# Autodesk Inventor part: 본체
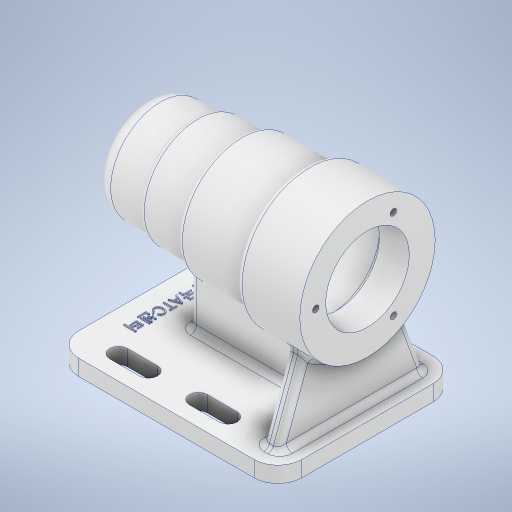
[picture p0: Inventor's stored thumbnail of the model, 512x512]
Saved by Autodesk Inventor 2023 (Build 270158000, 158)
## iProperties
Created: 2022-07
Part Number: 본체
Material: 알루미늄 6061
Document SubType Name: Modeling
Designer: owner
Density: 2.7 g/cm^3
Appearance: 알루미늄 - 평지
Mass: 695.707 g
Surface Area: 710.79 cm^2
Volume: 257.669 cm^3
Author: owner
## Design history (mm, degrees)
sketch "스케치1"
  geometry: L1 (0, 0)-(0, 34); L2 (0, 34)-(-32, 34); L3 (-32, 34)-(-32, 30); L4 (-32, 30)-(-66, 30); L5 (-66, 30)-(-66, 27); L6 (-66, 27)-(-88, 27); L7 (-88, 27)-(-88, 25); L8 (-88, 25)-(-104, 25); L9 (-112, 17)-(-112, 0); L10 (-112, 0)-(0, 0); L11 (0, 21)-(-15, 21); L12 (-15, 21)-(-15, 21); L13 (-18, 24)-(-66, 24); L14 (-69, 21)-(-69, 21); L15 (-69, 21)-(-80.7, 21); L16 (-81, 20.7)-(-81, 17.5); L17 (-81, 17.5)-(-98.7, 17.5); L18 (-99, 17.2)-(-99, 16); L19 (-99, 16)-(-102.7, 16); L20 (-103, 15.7)-(-103, 10.5); L21 (-103, 10.5)-(-103, 10.5); L22 (-106, 7.5)-(-106, 0); A1 r 8 centre (-104, 17) between (-104, 25) and (-112, 17); A2 r 0.3 centre (-102.7, 15.7) between (-102.7, 16) and (-103, 15.7); A3 r 0.3 centre (-98.7, 17.2) between (-98.7, 17.5) and (-99, 17.2); A4 r 0.3 centre (-80.7, 20.7) between (-80.7, 21) and (-81, 20.7); A5 r 3 centre (-66, 21) between (-66, 24) and (-69, 21); A6 r 3 centre (-18, 21) between (-15, 21) and (-18, 24); A7 r 3 centre (-103, 7.5) between (-103, 10.5) and (-106, 7.5); 4 further points
  constraints: 44 end point, 19 perpendicular, 14 point on circle, 14 tangent, 7 centre point, 4 equal radius, 4 point on line, 2 vertical, 1 horizontal
  dimensions: "d0" = 34 distance of L1.start L1.end; "d1" = 25 distance between parallel lines of L10 L8; "d2" = 112 distance between parallel lines of L1 L9; "d3" = 24 distance between parallel lines of L7 L9; "d4" = 22 distance between parallel lines of L5 L7; "d5" = 34 distance between parallel lines of L3 L5; "d6" = 27 distance between parallel lines of L10 L6; "d7" = 30 distance between parallel lines of L10 L4; "d8" = 21 distance between parallel lines of L10 L11; "d9" = 15 distance between parallel lines of L1 L12; "d10" = 54 distance between parallel lines of L14 L12; "d11" = 24 distance between parallel lines of L10 L13; "d12" = 12 distance between parallel lines of L16 L14; "d13" = 21 distance between parallel lines of L10 L15; "d14" = 18 distance between parallel lines of L18 L16; "d15" = 17.5 distance between parallel lines of L10 L17; "d16" = 10.5 distance between parallel lines of L10 L21; "d17" = 4 distance of L18.end point (-103, 16); "d18" = 16 distance between parallel lines of L10 L19; "d19" = 3 distance between parallel lines of L22 L20; "d20" = 8 radius of A1; "d21" = 0.3 radius of A2; "d22" = 3 radius of A5
revolve "회전1" sketch "스케치1" stored, may be unused: angle "d23" = 90 deg
node "작업 평면1"
sketch "스케치2"
  geometry: L1 (0, 0)-(0, -45); L2 (0, -45)-(112, -45); L3 (112, -45)-(112, 0); L4 (112, 0)-(0, 0); L5 (0, 45)-(112, 45); L6 (112, 45)-(112, 0); L7 (0, 0)-(0, 45)
  constraints: 14 end point, 2 perpendicular, 2 symmetric about line, 2 vertical
  dimensions: "d27" = 45 distance between parallel lines of L4 L2; "d28" = 112 distance between parallel lines of L1 L3
extrude "돌출1" join sketch "스케치2" distance "d29" = 8; taper "d30" = 0 deg
fillet "모깎기1" dims "d31" = 12
sketch "스케치4"
  geometry: 1 further point
sketch "스케치5"
  geometry: L1 (-92, -33)-(-77, -33); L2 (-92, -37.5)-(-77, -37.5); L3 (-77, -28.5)-(-92, -28.5); L4 (-112, 33)-(-112, -33) reference; L5 (-100, -45)-(-12, -45) reference; L6 (-52, -33)-(-37, -33); L7 (-52, -37.5)-(-37, -37.5); L8 (-37, -28.5)-(-52, -28.5); L9 (-92, 33)-(-77, 33); L10 (-92, 28.5)-(-77, 28.5); L11 (-77, 37.5)-(-92, 37.5); L12 (-12, 45)-(-100, 45) reference; L13 (-52, 33)-(-37, 33); L14 (-52, 28.5)-(-37, 28.5); L15 (-37, 37.5)-(-52, 37.5); A1 r 4.5 centre (-92, -33) between (-92, -28.5) and (-92, -37.5); A2 r 4.5 centre (-77, -33) between (-77, -37.5) and (-77, -28.5); A3 r 4.5 centre (-52, -33) between (-52, -28.5) and (-52, -37.5); A4 r 4.5 centre (-37, -33) between (-37, -37.5) and (-37, -28.5); A5 r 4.5 centre (-92, 33) between (-92, 37.5) and (-92, 28.5); A6 r 4.5 centre (-77, 33) between (-77, 28.5) and (-77, 37.5); A7 r 4.5 centre (-52, 33) between (-52, 37.5) and (-52, 28.5); A8 r 4.5 centre (-37, 33) between (-37, 28.5) and (-37, 37.5); 5 further points
  constraints: 32 end point, 16 point on circle, 16 tangent, 8 centre point, 4 horizontal, 4 midpoint, 4 parallel
  dimensions: "d38" = 9 diameter of A2; "d39" = 20 distance from line of L1.start L4; "d40" = 12 distance from line of L5 point (-84.5, -33); "d41" = 15 distance of L1.end L1.start; "d42" = 7.5 distance of point (-44.5, -33) L6.end; "d43" = 9 diameter of A4; "d44" = 25 distance of L6.start L1.end; "d45" = 12 distance from line of L5 L6.end; "d46" = 7.5 distance of point (-84.5, 33) L9.end; "d47" = 9 diameter of A6; "d48" = 20 distance from line of L4 L9.start; "d49" = 12 distance from line of point (-84.5, 33) L12; "d50" = 7.5 distance of point (-44.5, 33) L13.end; "d51" = 9 diameter of A8; "d52" = 25 distance of L13.start L9.end; "d53" = 12 distance between parallel lines of L12 L13
extrude "돌출2" cut sketch "스케치5" distance "d54" = 10; taper "d55" = 0 deg
node "작업 평면2"
sketch "스케치8"
  geometry: L1 (-62, 45)-(-62, 33) reference; L2 (-62, 37)-(-24.658, 23.409); L3 (-62, 45)-(-70, 45) reference; L4 (-24.658, -23.409)-(-62, -37); L5 (-62, -33)-(-62, -45) reference; L6 (-70, -45)-(-62, -45) reference; L7 (-62, -28.5)-(-62, -37.5) reference; L8 (-62, 37)-(-62, -37.5); A1 r 34 centre (0, 0) between (-24.658, 23.409) and (-24.658, -23.409) reference; 5 further points
  constraints: 6 end point, 2 point on line, 1 point on circle, 2 other
  dimensions: "d57" = 8 distance from line of L3 L2.start; "d58" = 110 deg angle of L1 L2; "d59" = 8 distance from line of L6 L4.end; "d60" = 110 deg angle of L5 L4
extrude "돌출3" join sketch "스케치8" distance "d61" = 8; taper "d62" = 0 deg
node "작업 평면3"
node "작업 평면4"
sketch "스케치11"
  geometry: L1 (16, -4)-(85, -4); L2 (85, -4)-(85, 4); L3 (85, 4)-(16, 4); L4 (16, 4)-(16, -4); 2 further points
  constraints: 8 end point, 3 perpendicular, 1 horizontal, 1 horizontal alignment, 1 midpoint
  dimensions: "d70" = 16 distance from line of L4 point (0, 0); "d71" = 8 distance between parallel lines of L3 L1; "d72" = 69 distance between parallel lines of L2 L4
extrude "돌출4" join sketch "스케치11" stored distance "d73" = 8; taper "d74" = 0 deg
fillet "모깎기2" dims "d75" = 3
fillet "모깎기3" dims "d76" = 3
fillet "모깎기4" dims "d77" = 3
sketch "스케치12" dims "d85" = 52
  geometry: 3 further points
  constraints: 2 horizontal alignment, 1 coincident, 2 other
hole "구멍1" sketch "스케치12" at (-26, 0) diameter "d78" = 3.242; stored, may be unused: countersink angle "d82" = 90 deg, drill point angle "d84" = 118 deg; dims "d79" = 8, "d80" = 4, "d81" = 2, "d83" = 11
sketch "스케치14"
  geometry: L1 (-112, 33)-(-112, -33) reference; 3 further points
  constraints: 1 horizontal alignment, 1 midpoint, 1 other
  dimensions: "d89" = 12 distance from line of L1 point (-100, 0)
feature "엠보싱1" sketch "스케치14" dims "d0" = 34, "d1" = 25, "d2" = 112, "d3" = 24, "d4" = 22, "d5" = 34, "d6" = 27, "d7" = 30, "d8" = 21, "d9" = 15, "d10" = 54, "d11" = 24, "d12" = 12, "d13" = 21, "d14" = 18, "d15" = 17.5, "d16" = 10.5, "d17" = 4, "d18" = 16, "d19" = 3, "d20" = 8, "d21" = 0.3, "d22" = 3, "d90" = 0.5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
node "솔리드1"
pattern_circular "원형 패턴1" dims angle "d87" = 360 deg
feature "A9D066F2-1C7D-4E18-AEED-F7BC21143FA4" dims "d78" = 3.242, "d79" = 8, "d80" = 4, "d81" = 2, "d82" = 90 deg, "d83" = 11, "d84" = 118 deg
other parameters: "d56" = -8, "d63" = 62, "d64" = -62
